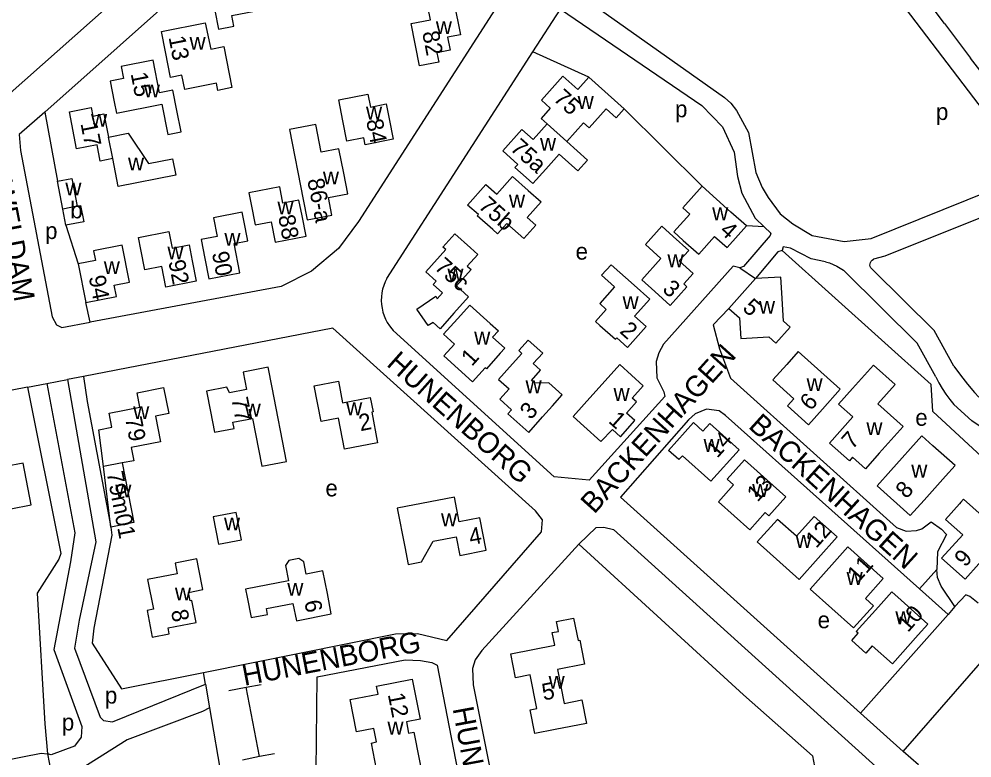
# Model space of a CAD drawing. Extents: x 157646 to 159241, y 379213 to 381217.
# Drawn here: x 158238.9 to 158467.5, y 380220.5 to 380397.8 of the extents above; entities that cross this region are included whole.
import ezdxf

# ---------------------------------------------------------------- set-up
doc = ezdxf.new("R2010")
doc.units = 0
for name, color, linetype in [('BLT_Basislijn', 7, 'Continuous'), ('BLT_Bebouwing', 7, 'Continuous'), ('BLT_Centroide', 7, 'Continuous'), ('BLT_Huisnummer', 7, 'Continuous'), ('BLT_Huisnummer_reeks', 7, 'Continuous'), ('BLT_Onderverdeling_panden', 7, 'Continuous'), ('BLT_Straatnaam', 7, 'Continuous')]:
    doc.layers.add(name, color=color, linetype=linetype)

msp = doc.modelspace()

# ---------------------------------------------------------------- linework, layer by layer
at = {"layer": 'BLT_Basislijn'}
for p, q in [((158460.93, 380396.74), (158452.27, 380408.29)), ((158362.2, 380389.9), (158368.81, 380400.14)), ((158460.93, 380396.74), (158467.16, 380388.36)), ((158327.16, 380335.54), (158362.2, 380389.9)), ((158375.62, 380383.81), (158362.2, 380389.9)), ((158478.7, 380373.54), (158467.16, 380388.36)), ((158384.11, 380376.23), (158402.77, 380357.65)), ((158417.71, 380347.9), (158413.42, 380348.12)), ((158411.86, 380338.04), (158415.58, 380335.5)), ((158255.93, 380325.04), (158254.88, 380329.72)), ((158240.91, 380309.41), (158245.58, 380310.33)), ((158245.58, 380310.33), (158250.55, 380311.27)), ((158254.33, 380312.03), (158250.55, 380311.27)), ((158459.1, 380265.72), (158454.92, 380261.01)), ((158454.92, 380261.01), (158461.84, 380254.9)), ((158463.43, 380256.85), (158461.84, 380254.9)), ((158461.84, 380254.9), (158440.79, 380231.18)), ((158283.6, 380238.14), (158283.13, 380241)), ((158283.6, 380238.14), (158284.62, 380232.52)), ((158289.23, 380236.69), (158293.37, 380237.45)), ((158293.37, 380237.45), (158296.97, 380238.12)), ((158296.6, 380220.78), (158293.37, 380237.45)), ((158284.62, 380232.52), (158287.97, 380212.97)), ((158451.02, 380222.02), (158440.79, 380231.18)), ((158245.75, 380221.43), (158249.8, 380199.83)), ((158300.17, 380221.49), (158296.6, 380220.78)), ((158454.67, 380218.81), (158451.02, 380222.02)), ((158296.6, 380220.78), (158292.5, 380219.97))]:
    msp.add_line(p, q, dxfattribs=at)
for points in [[(158231.68, 380375.57), (158289.69, 380427.01), (158297.95, 380435.63)], [(158245.11, 380375.43), (158298.61, 380423.12), (158303.1, 380427.63), (158305.95, 380431.25)], [(158371.84, 380404.74), (158408.18, 380378.92), (158409.65, 380377.6), (158411.02, 380375.86), (158413.89, 380370.53), (158415.7, 380360.95), (158417.2, 380357.34), (158418.61, 380354.92), (158421.49, 380351.01), (158424.52, 380348.6), (158429.22, 380345.84), (158436.86, 380344.43), (158443.38, 380345.1), (158477.93, 380359), (158481.57, 380360.73), (158481.57, 380361.05), (158447.97, 380405.16)], [(158353.1, 380400.13), (158320.33, 380349.18), (158315.53, 380342.75), (158309.04, 380337.25), (158301.78, 380333.59), (158255.93, 380325.04)], [(158368.81, 380400.14), (158402.75, 380377.05), (158407.65, 380371.93), (158410.45, 380365.82), (158411.25, 380359.98), (158412.3, 380355.98), (158415.5, 380350.01), (158417.71, 380347.9)], [(158245.11, 380375.43), (158238.94, 380370.05), (158239.27, 380366.22), (158246.87, 380326.28), (158247.91, 380324.41), (158249.12, 380323.74), (158255.93, 380325.04)], [(158245.11, 380375.43), (158248.08, 380358.84)], [(158475.81, 380352.18), (158471.19, 380350.72), (158446.66, 380340.84), (158443.91, 380340.14)], [(158250.15, 380348.29), (158253.06, 380339.02)], [(158417.71, 380347.9), (158419.24, 380346.43), (158419.14, 380345.87), (158412.74, 380338.36), (158411.86, 380338.04)], [(158432.42, 380339.49), (158428.97, 380340.21), (158424.02, 380342.82), (158422.2, 380343.11), (158421.98, 380342.26)], [(158421.98, 380342.26), (158420.99, 380341.94), (158415.58, 380335.5)], [(158481.47, 380282.03), (158458.15, 380303.58), (158457.75, 380310.07), (158421.98, 380342.26)], [(158443.74, 380337.59), (158443.48, 380337.8), (158443.27, 380338.07), (158443.12, 380338.38), (158443.06, 380338.71), (158443.07, 380339.05), (158443.17, 380339.38), (158443.33, 380339.68), (158443.56, 380339.93), (158443.91, 380340.14)], [(158411.86, 380338.04), (158410.23, 380338.49), (158393.53, 380319.77), (158392.39, 380317.64), (158391.75, 380315.6), (158391.88, 380311.67), (158393.56, 380308.34), (158393.84, 380307.18), (158375.71, 380287.12), (158367.27, 380287.96), (158328.65, 380323.02)], [(158432.42, 380339.49), (158433.33, 380339.24), (158434.22, 380338.91), (158435.07, 380338.5), (158435.89, 380338.03), (158436.67, 380337.49), (158437.03, 380337.2)], [(158327.16, 380335.54), (158326.74, 380334.71), (158326.4, 380333.85), (158326.13, 380332.96), (158325.94, 380332.06), (158325.83, 380331.14), (158325.8, 380330.21), (158325.85, 380329.29), (158325.98, 380328.37), (158326.18, 380327.47), (158326.46, 380326.59), (158326.82, 380325.73), (158327.25, 380324.92), (158327.75, 380324.14), (158328.32, 380323.4), (158328.65, 380323.02)], [(158458.88, 380311.93), (158454.42, 380320), (158437.03, 380337.2)], [(158463.19, 380314.47), (158458.45, 380323.05), (158443.74, 380337.59)], [(158409.22, 380328.34), (158405.45, 380324.36), (158406.94, 380318.66), (158409.59, 380311.59), (158449.43, 380275.77), (158451.75, 380274.9), (158454.2, 380275.01), (158455.47, 380275.45), (158457.78, 380277.14), (158460.25, 380275.39), (158461.42, 380274.11), (158459.29, 380269.89), (158459.1, 380265.72)], [(158283.13, 380241), (158329.2, 380250.25), (158334.46, 380250.32), (158341.56, 380248.63), (158364.28, 380274.74), (158364.51, 380277.62), (158362.79, 380279.75), (158314.16, 380323.59), (158254.33, 380312.03)], [(158463.19, 380314.47), (158464.79, 380312.31), (158466.45, 380310.2), (158468.17, 380308.13), (158469.14, 380307.03)], [(158245.58, 380310.33), (158252.3, 380274.46), (158251.24, 380267.51), (158247.21, 380246.5), (158253.94, 380227.98), (158253.77, 380225.42), (158252.16, 380223.3), (158246.58, 380221.23), (158245.75, 380221.43)], [(158250.55, 380311.27), (158257.34, 380272.3), (158253.3, 380253.51), (158252.18, 380246.82), (158258.35, 380230.27), (158259.14, 380229.47), (158261.31, 380229.16), (158283.6, 380238.14)], [(158254.33, 380312.03), (158255.2, 380306), (158260.95, 380275.88)], [(158458.88, 380311.93), (158459.61, 380310.51), (158460.4, 380309.13), (158461.27, 380307.8), (158462.2, 380306.5), (158463.19, 380305.26)], [(158240.91, 380309.41), (158153.5, 380292.29), (158150.86, 380290.66), (158149.82, 380288.98), (158149.37, 380286.11), (158164.48, 380209.59), (158169.09, 380202.74), (158196.52, 380212.25), (158244.17, 380221.61), (158245.75, 380221.43)], [(158240.91, 380309.41), (158248.91, 380269.54), (158248.45, 380268.17), (158243.2, 380260.04), (158245.05, 380228.66), (158245.75, 380221.43)], [(158454.92, 380261.01), (158408.42, 380302.67), (158406.85, 380303.77), (158403.86, 380304.17), (158401.12, 380303.07), (158399.53, 380301.64), (158383.24, 380283.03)], [(158481.47, 380282.03), (158481.25, 380288.98), (158480.71, 380290.51), (158477.43, 380294.71), (158467.51, 380301.4), (158463.19, 380305.26)], [(158383.24, 380283.03), (158440.79, 380231.18)], [(158260.95, 380275.88), (158261.12, 380273.93), (158256.84, 380251.58), (158256.42, 380248.04), (158263.44, 380237.08), (158283.13, 380241)], [(158373.23, 380271.73), (158377.36, 380275.74)], [(158377.36, 380275.74), (158379.22, 380275.84), (158381.49, 380275.3), (158450.28, 380213.1)], [(158373.23, 380271.73), (158349.9, 380246.28), (158348.35, 380244.02), (158347.67, 380241.92), (158347.84, 380237.99), (158358.11, 380186.78)], [(158373.23, 380271.73), (158412.74, 380235.62), (158429.29, 380220.95), (158435.73, 380186.46)], [(158463.43, 380256.85), (158460.12, 380261.66), (158459.23, 380263.78), (158459.1, 380265.72)], [(158469.05, 380257.58), (158467.05, 380259.19), (158466.07, 380259.61), (158463.43, 380256.85)], [(158451.02, 380222.02), (158476.16, 380250.79), (158475.78, 380251.67), (158472.99, 380254.17)], [(158287.97, 380212.97), (158310.18, 380217.38), (158310.44, 380239.93), (158331.53, 380244.04), (158335.23, 380243.88), (158337.92, 380243.39), (158339.2, 380242.71), (158352.77, 380172.49), (158353.08, 380169.65), (158351.9, 380168), (158349.58, 380166.98), (158311.74, 380159.34), (158311.36, 380158.17), (158313.7, 380147.1), (158314.88, 380144.45)], [(158284.62, 380232.52), (158282.88, 380231.62), (158264.87, 380224.82), (158253.82, 380217.82), (158251.93, 380216.52), (158251.89, 380215.95), (158256.2, 380193.96), (158272.17, 380175.99), (158272.83, 380174.27), (158281.18, 380139.35), (158281.49, 380133.38), (158279.67, 380125.01), (158279.83, 380123.35), (158281.2, 380121.37), (158282.85, 380120.29), (158284.12, 380120.29), (158285.4, 380121.19), (158296.44, 380135.38), (158300.19, 380137.95), (158307.59, 380138.72), (158313.99, 380143.42), (158314.88, 380144.45)]]:
    msp.add_lwpolyline(points, dxfattribs=at)
at = {"layer": 'BLT_Bebouwing'}
for p, q in [((158384.11, 380376.23), (158375.62, 380383.81)), ((158365.59, 380372.64), (158370.31, 380368.38)), ((158249.4, 380352.12), (158248.08, 380358.84)), ((158250.15, 380348.29), (158249.4, 380352.12)), ((158415.58, 380335.5), (158409.22, 380328.34))]:
    msp.add_line(p, q, dxfattribs=at)
for points in [[(158296.25, 380404.26), (158295.29, 380409.16), (158287.43, 380407.62), (158287.87, 380405.34), (158284.87, 380404.75), (158285.83, 380399.85), (158286.71, 380395.33), (158290.42, 380396.05), (158289.93, 380398.6), (158297.08, 380400), (158296.25, 380404.26)], [(158332.98, 380396.71), (158337.6, 380397.61), (158337, 380400.71), (158343.25, 380401.93), (158344.8, 380394), (158341.69, 380393.39), (158342.3, 380390.3), (158339.17, 380389.69), (158339.62, 380387.42), (158334.98, 380386.51), (158332.98, 380396.71)], [(158286.29, 380382.37), (158278.63, 380380.87), (158277.96, 380384.31), (158275.19, 380383.77), (158273.99, 380389.91), (158273.03, 380394.81), (158283.56, 380396.88), (158284.88, 380390.55), (158288.02, 380391.17), (158289.95, 380381.31), (158286.62, 380380.66), (158286.29, 380382.37)], [(158276.76, 380375.79), (158275.8, 380380.69), (158272.61, 380380.07), (158271.08, 380387.87), (158263.37, 380386.36), (158263.93, 380383.47), (158260.75, 380382.85), (158261.71, 380377.94), (158262.25, 380375.2), (158273.14, 380377.33), (158274.56, 380370.06), (158277.76, 380370.68), (158276.76, 380375.79)], [(158375.62, 380383.81), (158372.97, 380380.84), (158369.36, 380384.06), (158364.23, 380378.31), (158366.35, 380376.42), (158364.13, 380373.94), (158365.59, 380372.64)], [(158327.69, 380373.83), (158328.65, 380368.92), (158321.9, 380367.6), (158321.58, 380369.23), (158317.56, 380368.44), (158316.6, 380373.35), (158315.62, 380378.36), (158322.59, 380379.72), (158323.2, 380376.65), (158326.99, 380377.39), (158327.69, 380373.83)], [(158250.96, 380375.5), (158256.22, 380376.53), (158256.62, 380374.49), (158259.25, 380375), (158260.34, 380369.45)], [(158261.36, 380364.28), (158258.36, 380363.69), (158257.6, 380367.6), (158252.69, 380366.64), (158250.96, 380375.5)], [(158384.11, 380376.23), (158382.18, 380374.07), (158379.73, 380376.26), (158375.66, 380371.7), (158374.34, 380372.88), (158370.31, 380368.38)], [(158316.78, 380360.76), (158315.63, 380366.65), (158311.38, 380365.82), (158310.08, 380372.48), (158303.75, 380371.24)], [(158365.59, 380372.64), (158362.22, 380368.87), (158359.54, 380371.26), (158354.95, 380366.11), (158358.55, 380362.89), (158357.87, 380362.13), (158360.55, 380359.73), (158362.17, 380358.29), (158365.3, 380361.79), (158368.46, 380365.34), (158372.94, 380361.34), (158375.27, 380363.95), (158370.31, 380368.38)], [(158260.34, 380369.45), (158265.04, 380370.37), (158269.95, 380363.08), (158275.71, 380364.21), (158276.48, 380360.3), (158262.66, 380357.6), (158261.36, 380364.28)], [(158303.75, 380371.24), (158307.03, 380354.48), (158307.99, 380349.57), (158313.93, 380350.73), (158313.11, 380354.95), (158317.74, 380355.86), (158316.78, 380360.76)], [(158248.08, 380358.84), (158251.55, 380359.52), (158252.85, 380352.87)], [(158361.05, 380356.64), (158364.13, 380353.88), (158360.8, 380350.15), (158362.88, 380348.29), (158360.02, 380345.08), (158355.94, 380348.73), (158353.71, 380346.23), (158352.57, 380347.25), (158348.84, 380350.58), (158349.09, 380350.86), (158346.51, 380353.15), (158350.91, 380358.09), (158353.54, 380355.74), (158357.32, 380359.97), (158361.05, 380356.64)], [(158306.79, 380350.59), (158306.05, 380354.35), (158302.22, 380353.6), (158301.45, 380357.54), (158294, 380356.08), (158294.55, 380353.29), (158295.51, 380348.38), (158299.38, 380349.14), (158300.34, 380344.23), (158307.75, 380345.68), (158306.79, 380350.59)], [(158402.77, 380357.65), (158398.15, 380352.48), (158399.84, 380350.97), (158396, 380346.68), (158398.24, 380344.67), (158401.97, 380341.34), (158405.79, 380345.61), (158408.78, 380342.93), (158413.42, 380348.12)], [(158413.42, 380348.12), (158409.7, 380351.46), (158402.77, 380357.65)], [(158252.85, 380352.87), (158253.67, 380353.03), (158254.44, 380349.14), (158250.15, 380348.29)], [(158292.79, 380349.43), (158292.4, 380351.42), (158285.52, 380350.07), (158286.39, 380345.61), (158282.56, 380344.86), (158283.45, 380340.31), (158284.41, 380335.4), (158291.88, 380336.86), (158290.5, 380343.89), (158293.75, 380344.53), (158292.79, 380349.43)], [(158395.84, 380345.59), (158393.12, 380348.04), (158389.18, 380343.65), (158392.89, 380340.32), (158388.28, 380335.18), (158391.4, 380332.39), (158395.12, 380329.05), (158399.14, 380333.53), (158398.38, 380334.21), (158400.65, 380336.74), (158397.31, 380339.74), (158399.56, 380342.25), (158395.84, 380345.59)], [(158280.45, 380339.75), (158281.41, 380334.84), (158274.09, 380333.41), (158273.12, 380338.36), (158269.1, 380337.57), (158268.13, 380342.47), (158267.57, 380345.36), (158274.82, 380346.78), (158275.59, 380342.81), (158279.69, 380343.62), (158280.45, 380339.75)], [(158347.19, 380342.91), (158348.99, 380341.29), (158346.44, 380338.46), (158347.34, 380337.65), (158343.82, 380333.73), (158346.76, 380331.09), (158343.25, 380327.19), (158339.91, 380323.47), (158338.29, 380324.99), (158337.05, 380324.2), (158334.36, 380328.16), (158338.91, 380331.24), (158339.22, 380330.64), (158340.49, 380332.07), (158338.22, 380334.1), (158338.94, 380334.91), (158336.5, 380337.1), (158341.3, 380342.45), (158340.61, 380343.06), (158343.47, 380346.24), (158347.19, 380342.91)], [(158254.88, 380329.72), (158262.24, 380331.16), (158261.71, 380333.91), (158265.39, 380334.63), (158263.66, 380343.48), (158256.77, 380342.13), (158257.22, 380339.83), (158253.06, 380339.02)], [(158253.06, 380339.02), (158254.88, 380329.72)], [(158386.47, 380333.88), (158380.94, 380338.82), (158378.67, 380336.29), (158381.8, 380333.49), (158378.22, 380329.48), (158379.77, 380328.1), (158377.2, 380325.22), (158378.27, 380324.26), (158381.99, 380320.93), (158382.31, 380321.28), (158384.87, 380318.99), (158389.32, 380323.96), (158386.54, 380326.45), (158390.2, 380330.54), (158386.47, 380333.88)], [(158409.22, 380328.34), (158411.75, 380326.09), (158412.05, 380321.08), (158418.77, 380321.48), (158420.45, 380319.99), (158423.88, 380323.85), (158422.29, 380325.27), (158421.88, 380332.09), (158421.66, 380335.87), (158415.58, 380335.5)], [(158354.36, 380317.57), (158351.01, 380313.85), (158350.74, 380314.1), (158347.71, 380310.73), (158340.79, 380316.94), (158343.34, 380319.78), (158340.74, 380322.14), (158344.08, 380325.86), (158347.03, 380329.15), (158351.95, 380324.73), (158353.9, 380322.98), (158352.51, 380321.43), (158355.45, 380318.79), (158354.36, 380317.57)], [(158364.51, 380302.31), (158366.88, 380304.95), (158369.23, 380307.57), (158366.01, 380310.47), (158362.62, 380310.4), (158361.87, 380311.06), (158364.04, 380313.48), (158362.25, 380315.09), (158364.53, 380317.63), (158361.05, 380320.75), (158358.77, 380318.21), (158359.55, 380317.51), (158357.3, 380315.01), (158353.96, 380311.29), (158356.48, 380309.03), (158354.24, 380306.54), (158357.03, 380304.04), (158356.16, 380303.08), (158361.17, 380298.59), (158364.51, 380302.31)], [(158431.64, 380304.15), (158435.93, 380308.93), (158425.85, 380317.97), (158423.09, 380314.9), (158419.76, 380311.18), (158424.78, 380306.68), (158423.24, 380304.97), (158428.31, 380300.43), (158431.64, 380304.15)], [(158386.66, 380301.45), (158384.64, 380303.22), (158387, 380305.92), (158386.03, 380306.78), (158388.66, 380309.78), (158383.04, 380314.9), (158374.5, 380305.39), (158371.82, 380302.4), (158374.42, 380300.09), (158378.52, 380296.43), (158381.3, 380299.27), (158383.24, 380297.56), (158386.66, 380301.45)], [(158299.6, 380309.33), (158298.65, 380314.23), (158292.68, 380313.07), (158293.49, 380308.92), (158289.41, 380308.12), (158288.75, 380309.45), (158283.9, 380308.51), (158284.85, 380303.6), (158285.82, 380298.62), (158290.47, 380299.52), (158290.18, 380301.02), (158294.94, 380301.94), (158297.17, 380290.49), (158303.05, 380291.63), (158299.6, 380309.33)], [(158445.3, 380293.6), (158441.97, 380289.87), (158438.9, 380292.61), (158438.12, 380291.74), (158433.34, 380296), (158438.97, 380302.29), (158435.54, 380305.36), (158438.87, 380309.09), (158443.9, 380314.72), (158449.08, 380310.09), (158444.96, 380305.48), (158451.05, 380300.03), (158445.3, 380293.6)], [(158309.73, 380309.74), (158315.53, 380310.87), (158316.53, 380305.71), (158323.16, 380307), (158323.83, 380303.55), (158323.5, 380303.48), (158324.93, 380296.11), (158317, 380294.57), (158315.55, 380302.01), (158311.39, 380301.2), (158309.73, 380309.74)], [(158260.5, 380303.23), (158267.88, 380304.67), (158267.21, 380308.1), (158273.58, 380309.34), (158274.79, 380303.09), (158271.63, 380302.47), (158272.83, 380296.3), (158265.82, 380294.94), (158266.42, 380291.8), (158263.65, 380291.28)], [(158259.15, 380290.41), (158258.05, 380299.23), (158261.17, 380299.82), (158260.5, 380303.23)], [(158404.89, 380286.88), (158398.04, 380293), (158397.19, 380292.05), (158394.74, 380294.25), (158400.72, 380300.95), (158402.98, 380298.92), (158404.6, 380300.73), (158411.65, 380294.44), (158404.89, 380286.88)], [(158236.88, 380280.28), (158241.79, 380281.24), (158239.84, 380291.23), (158235.67, 380290.41), (158234.75, 380295.17), (158228.08, 380293.87), (158227.44, 380297.14), (158221.17, 380295.92), (158222.35, 380289.86), (158221.03, 380289.6), (158221.99, 380284.69), (158222.36, 380282.82), (158226.84, 380283.69), (158226.47, 380285.58), (158229.42, 380286.15), (158229.61, 380285.2), (158234.09, 380286.07), (158235.28, 380279.97), (158236.88, 380280.28)], [(158456.06, 380282.34), (158461.2, 380288.08), (158463.48, 380290.63), (158458.17, 380295.38), (158455.51, 380297.76), (158448.08, 380289.47), (158444.75, 380285.74), (158452.73, 380278.61), (158456.06, 380282.34)], [(158408.76, 380287.37), (158410.31, 380285.99), (158406.71, 380281.95), (158414.23, 380275.23), (158417.9, 380279.33), (158418.8, 380278.53), (158422.89, 380283.1), (158412.92, 380292.02), (158408.76, 380287.37)], [(158260.95, 380275.88), (158259.15, 380290.41)], [(158263.65, 380291.28), (158266.4, 380276.93), (158260.95, 380275.88)], [(158329.62, 380280.4), (158331.43, 380271.12), (158332.25, 380266.89), (158335.45, 380267.51), (158338.24, 380272.45), (158343.78, 380273.53), (158344.65, 380269.06), (158350.95, 380270.29), (158349.42, 380278.11), (158344.5, 380277.15), (158343.35, 380283.07), (158329.62, 380280.4)], [(158469.21, 380267.07), (158475.27, 380273.85), (158465.52, 380282.57), (158464.89, 380281.86), (158464.51, 380281.44), (158461.18, 380277.71), (158465.31, 380274.03), (158460.25, 380268.37), (158465.88, 380263.34), (158469.21, 380267.07)], [(158420.87, 380277.72), (158416.02, 380272.3), (158426.06, 380263.32), (158435.17, 380273.51), (158429.66, 380278.43), (158425.4, 380273.67), (158420.87, 380277.72)], [(158428.68, 380261), (158439.13, 380251.67), (158443.9, 380257.01), (158441.96, 380258.74), (158446.23, 380263.51), (158437.73, 380271.11), (158428.68, 380261)], [(158282, 380265.76), (158281.52, 380268.21), (158276.36, 380267.21), (158276.85, 380264.68), (158269.73, 380263.3), (158271.12, 380256.14), (158269.6, 380255.85), (158270.84, 380249.46), (158274.91, 380250.25), (158274.63, 380251.69), (158281.36, 380253), (158280.33, 380258.25), (158279.93, 380258.17), (158279.54, 380260.19), (158282.95, 380260.86), (158282, 380265.76)], [(158312.86, 380259.93), (158311.8, 380265.38), (158307.8, 380264.6), (158307.22, 380267.54), (158306.05, 380268.33), (158303.61, 380267.86), (158302.82, 380266.68), (158303.54, 380262.96), (158293.23, 380260.96), (158293.6, 380259.06), (158294.56, 380254.15), (158298.5, 380254.92), (158298.23, 380256.3), (158304.62, 380257.54), (158305.43, 380253.39), (158313.81, 380255.02), (158312.86, 380259.93)], [(158448.44, 380243.05), (158443.62, 380247.36), (158442.08, 380245.64), (158438.68, 380248.67), (158440.22, 380250.4), (158439.78, 380250.79), (158445.09, 380256.74), (158448.3, 380260.35), (158450.55, 380258.34), (158456.97, 380252.6)], [(158374.42, 380243.8), (158374.58, 380242.97), (158368.07, 380241.69), (158369.68, 380233.55), (158373.95, 380234.39), (158375.06, 380228.75), (158367.56, 380227.27), (158362.66, 380226.3), (158361.53, 380232), (158363.14, 380232.32), (158361.54, 380240.43), (158357.98, 380239.73), (158356.86, 380245.43), (158367.43, 380247.52), (158366.83, 380250.56), (158368.3, 380250.85), (158367.83, 380253.22), (158371.95, 380254.03), (158373.01, 380248.62), (158373.45, 380248.7), (158374.42, 380243.8)], [(158456.97, 380252.6), (158454.65, 380250), (158448.44, 380243.05)], [(158318.34, 380234.49), (158325.03, 380235.81), (158324.65, 380237.7), (158333.2, 380239.39), (158335.1, 380229.75), (158331.84, 380229.11), (158332.37, 380226.42), (158333.65, 380226.68), (158336.21, 380213.69), (158332.6, 380212.98), (158332.22, 380214.92), (158325.49, 380213.59), (158323.43, 380224.05), (158324.68, 380224.3), (158324.03, 380227.56), (158319.89, 380226.74), (158318.34, 380234.49)]]:
    msp.add_lwpolyline(points, dxfattribs=at)
msp.add_lwpolyline([(158291.01, 380279.39), (158285.46, 380278.32), (158286.73, 380271.74), (158292.28, 380272.81)], close=True, dxfattribs=at)
at = {"layer": 'BLT_Onderverdeling_panden'}
for p, q in [((158261.36, 380364.28), (158260.34, 380369.45)), ((158252.85, 380352.87), (158249.4, 380352.12)), ((158263.65, 380291.28), (158259.15, 380290.41))]:
    msp.add_line(p, q, dxfattribs=at)

# ---------------------------------------------------------------- texts
at = {"layer": 'BLT_Centroide'}
for s, p in [('w', (158338.89, 380394.17)), ('w', (158279.8, 380390.39)), ('w', (158268.83, 380378.97)), ('w', (158372.92, 380376.22)), ('w', (158322.14, 380373.64)), ('p', (158396.29, 380374.2)), ('p', (158458.89, 380373.55)), ('w', (158256.16, 380371.91)), ('w', (158363.89, 380366.19)), ('w', (158265.03, 380361.44)), ('w', (158311.8, 380358.11)), ('w', (158250, 380355.44)), ('b', (158251.19, 380349.95)), ('w', (158300.88, 380350.89)), ('w', (158356.44, 380352.53)), ('w', (158405.2, 380349.5)), ('p', (158245.14, 380344.99)), ('w', (158288.16, 380343.36)), ('w', (158274.48, 380340.11)), ('e', (158372.42, 380340.04)), ('w', (158394.47, 380338.22)), ('w', (158259.22, 380336.59)), ('w', (158341.67, 380334.84)), ('w', (158383.7, 380328.19)), ('w', (158416.43, 380327.06)), ('w', (158348.09, 380319.67)), ('w', (158360.42, 380307.98)), ('w', (158427.84, 380308.52)), ('w', (158381.53, 380306.14)), ('w', (158317.37, 380302.72)), ('w', (158266.27, 380301.78)), ('w', (158293.02, 380302.38)), ('e', (158453.93, 380300.18)), ('w', (158442.2, 380297.94)), ('w', (158403.14, 380293.91)), ('w', (158452.97, 380287.76)), ('w', (158261.98, 380282.97)), ('e', (158312.4, 380283.23)), ('w', (158414.8, 380283.11)), ('w', (158340.14, 380276.06)), ('w', (158288.06, 380275.07)), ('w', (158425.21, 380270.88)), ('w', (158437.45, 380261.98)), ('w', (158303.25, 380259.38)), ('w', (158276.28, 380258.28)), ('w', (158449.16, 380252.56)), ('e', (158430.5, 380251.59)), ('w', (158365.95, 380237.09)), ('p', (158259.49, 380233.51)), ('p', (158249.16, 380227.06)), ('w', (158327.28, 380226.08))]:
    msp.add_text(s, height=4, dxfattribs=at).set_placement(p)
at = {"layer": 'BLT_Huisnummer'}
for s, rotation, p in [('82', 281.0883, (158335.61, 380394.56)), ('13', 281.0892, (158274.74, 380393.4)), ('15', 281.0892, (158265.65, 380384.67)), ('75', 318.2558, (158366.88, 380378.38)), ('17', 281.0892, (158253.62, 380372.72)), ('84', 281.0883, (158322.15, 380373.44)), ('75a', 318.2621, (158356.51, 380366.49)), ('75b', 318.2675, (158348.88, 380352.62)), ('88', 281.0883, (158301.04, 380350.44)), ('4', 318.1686, (158406.77, 380346.67)), ('92', 281.0883, (158274.7, 380339.62)), ('90', 281.0883, (158285.15, 380341.64)), ('75c', 318.0894, (158338.34, 380337.96)), ('94', 281.0883, (158255.59, 380335.91)), ('3', 318.0724, (158393.02, 380332.65)), ('5', 318.3707, (158412.26, 380328.13)), ('2', 318.178, (158382.79, 380322.64)), ('1', 48.0801, (158347.55, 380314.28)), ('6', 48.121, (158428.81, 380303.58)), ('77', 281.0132, (158289.81, 380306.68)), ('3', 48.0962, (158361.65, 380301.43)), ('2', 11.018, (158320.8, 380298.86)), ('1', 318.3128, (158380.09, 380301.11)), ('14', 48.2011, (158406.41, 380292.23)), ('7', 48.121, (158438.84, 380294.34)), ('13', 48.2011, (158416.09, 380281.72)), ('8', 48.121, (158451.79, 380282.46)), ('12', 48.2011, (158430.18, 380270.61)), ('4', 11.0121, (158347.23, 380271.51)), ('9', 48.121, (158465.9, 380266.06)), ('11', 48.2011, (158440.15, 380262.29)), ('6', 281.011, (158307.31, 380258.01)), ('8', 281.0071, (158275.33, 380255.74)), ('10', 48.2011, (158452.15, 380250.41)), ('5', 11.1408, (158364.75, 380234.24)), ('12', 281.3028, (158327.35, 380235.72))]:
    msp.add_text(s, height=4, rotation=rotation, dxfattribs=at).set_placement(p)
at = {"layer": 'BLT_Huisnummer_reeks'}
for s, rotation, p in [('86-a', 281.0883, (158308.03, 380359.2)), ('79', 281.0165, (158264.32, 380301.98)), ('79m01', 281.0165, (158259.88, 380288.88))]:
    msp.add_text(s, height=4, rotation=rotation, dxfattribs=at).set_placement(p)
at = {"layer": 'BLT_Straatnaam'}
for s, rotation, p in [('WELDAM', 280.8093, (158232.35, 380358.51)), ('BACKENHAGEN', 47.9422, (158376.9, 380278.82)), ('HUNENBORG', 318.3631, (158326.83, 380314.74)), ('BACKENHAGEN', 317.8227, (158413.65, 380299.82)), ('HUNENBORG', 11.0114, (158292.94, 380237.76)), ('HUNENBORG', 280.4406, (158342.91, 380232.34))]:
    msp.add_text(s, height=5, rotation=rotation, dxfattribs=at).set_placement(p)

doc.saveas('drawing.dxf')
